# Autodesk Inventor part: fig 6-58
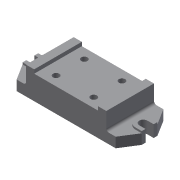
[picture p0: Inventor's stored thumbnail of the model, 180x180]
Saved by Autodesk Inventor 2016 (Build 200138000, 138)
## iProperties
Shininess: 77.0
Angle Display Precision: 2
Document Length Units: 11269
Document Angle Units: 11279
Document Time Units: 11290
Document Mass Units: 11283
Document Length Units Precision: 3
Document Angle Units Precision: 2
Created: 2001-12
Part Number: fig 6-58
Document SubType Name: Modeling
Designer: Renu Muthoo
Density: 1 g/cm^3
Material: Generic
Appearance: Default
Density: 0.0
Volumn: 0.0
Area: 0.0
PropertySet Name: Model Information
Control State: 0
Master: False
Checked Out: False
Author: Renu Muthoo
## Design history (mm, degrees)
sketch "Sketch3"
  geometry: L1 (-59.119, -24.322)-(-59.119, 19.678); L2 (-59.119, 19.678)-(-46.119, 19.678); L3 (-46.119, 19.678)-(-46.119, 13.678); L4 (-46.119, 13.678)-(55.881, 13.678); L5 (55.881, 13.678)-(55.881, 19.678); L6 (55.881, 19.678)-(68.881, 19.678); L7 (68.881, 19.678)-(68.881, -24.322); L8 (68.881, -24.322)-(-59.119, -24.322)
  constraints: 16 end point, 2 equal length
  dimensions: "d10" = 13 distance of L1.end L2.end; "d11" = 102 distance of L3.end L4.end; "d13" = 44 distance between parallel lines of L2 L8; "d14" = 6 distance of L2.end L3.end
extrude "Extrusion1" new body sketch "Sketch3" distance "d15" = 76; taper "d16" = 0 deg
sketch "Sketch4"
  geometry: L1 (0, 0)-(0, 76) reference; L2 (0, 76)-(-15, 76); L3 (-15, 76)-(-31, 50.5); L4 (-31, 50.5)-(-31, 44.5); L5 (-31, 44.5)-(-21, 44.5); L6 (-21, 31.5)-(-31, 31.5); L7 (-31, 31.5)-(-31, 25.5); L8 (-31, 25.5)-(-15, 0); L9 (-15, 0)-(0, 0); L10 (128, 76)-(0, 76) reference; L11 (0, 0)-(128, 0) reference; A1 r 6.5 centre (-21, 38) between (-21, 31.5) and (-21, 44.5)
  constraints: 16 end point, 4 equal length, 3 collinear, 3 parallel, 2 perpendicular, 2 point on circle, 2 tangent, 1 centre point
  dimensions: "d17" = 13 distance between parallel lines of L6 L5; "d18" = 25 distance of L3.end L7.end; "d19" = 10 distance of L6.start L6.end; "d20" = 15 distance of L8.end L1.start; "d21" = 16 horizontal distance of L7.end L8.end
extrude "Extrusion2" join sketch "Sketch4" distance "d22" = 16; taper "d23" = 0 deg
sketch "Sketch5"
  geometry: L1 (-159, 44.5)-(-159, 50.5) reference; L2 (-149, 44.5)-(-159, 44.5) reference; L3 (-159, 31.5)-(-149, 31.5) reference; L4 (-159, 25.5)-(-159, 31.5) reference; L5 (-159, 25.5)-(-149, 25.5); L6 (-149, 50.5)-(-159, 50.5); A1 r 6.5 centre (-149, 38) between (-149, 31.5) and (-149, 44.5) reference; A2 r 12.5 centre (-149, 38) between (-149, 25.5) and (-149, 50.5)
  constraints: 4 end point, 2 point on circle, 2 tangent, 1 centre point, 1 parallel, 1 perpendicular
extrude "Extrusion3" join sketch "Sketch5" distance "d24" = 19; taper "d25" = 0 deg
workplane "Work Plane1"
mirror "Mirror1"
fillet "Fillet1" dims "d27" = 4
sketch "Sketch6"
  geometry: L1 (0, 0)-(0, 76) reference; L2 (0, 0)-(102, 0) reference; 1 further point
  dimensions: "d28" = 20 distance from line of L1 point (20, 15); "d29" = 15 distance from line of L2 point (20, 15)
hole "Hole1" sketch "Sketch6" at (20, 15) diameter "d30" = 10; stored, may be unused: countersink angle "d34" = 82 deg, drill point angle "d36" = 118 deg; dims "d31" = 6, "d32" = 4, "d33" = 2, "d35" = 15
sketch "Sketch7"
  geometry: C1 r 5 at (20, 15) reference; 3 further points
  constraints: 4 other
pattern_linear "Rectangular Pattern2" dims "d45" = 45
body "Solid1"
other parameters: "d26" = -64
